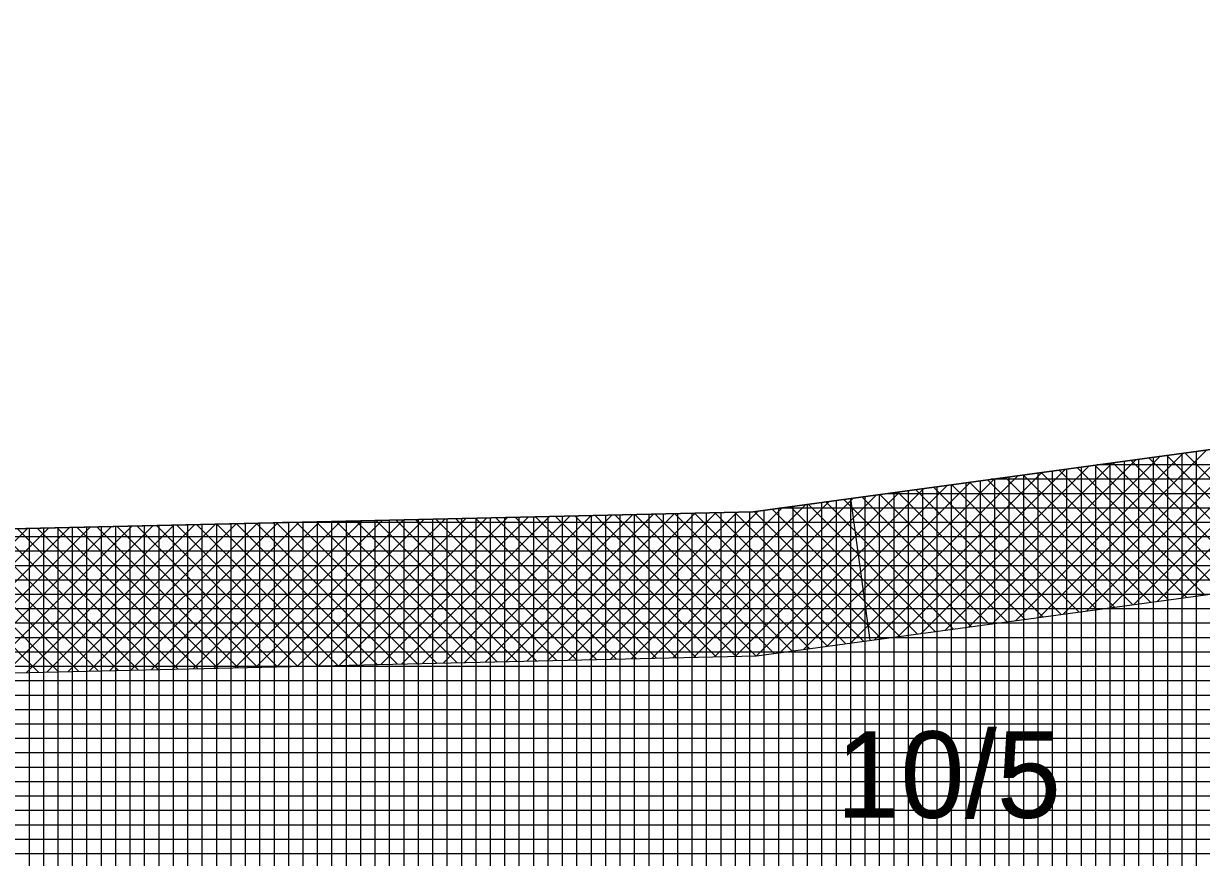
# Model space of a CAD drawing. Extents: x -565346 to -564154, y -1097386 to -1095620.
# Drawn here: x -565241.4 to -565225.05, y -1095860.99 to -1095849.41 of the extents above; entities that cross this region are included whole.
import ezdxf

# ---------------------------------------------------------------- set-up
doc = ezdxf.new("R2010")
doc.units = 0
for name, color, linetype in [('Vrstva 13', 7, 'Continuous'), ('Vrstva 40', 7, 'Continuous'), ('Vrstva 41', 7, 'Continuous'), ('Vrstva 42', 7, 'Continuous'), ('Vrstva 43', 7, 'Continuous')]:
    doc.layers.add(name, color=color, linetype=linetype)

msp = doc.modelspace()

# ---------------------------------------------------------------- linework, layer by layer
at = {"layer": 'Vrstva 13'}
for p, q in [((-565231.27, -1095856.19), (-565188.3, -1095850.34)), ((-565311.82, -1095858.04), (-565231.27, -1095856.19))]:
    msp.add_line(p, q, dxfattribs=at)
at = {"layer": 'Vrstva 41'}
for p, q in [((-565223.663, -1095855.154), (-565225.986, -1095857.478)), ((-565223.336, -1095855.11), (-565225.659, -1095857.433)), ((-565223.008, -1095855.065), (-565225.332, -1095857.389)), ((-565224.973, -1095855.333), (-565227.295, -1095857.655)), ((-565224.645, -1095855.288), (-565226.968, -1095857.611)), ((-565224.318, -1095855.244), (-565226.641, -1095857.567)), ((-565223.99, -1095855.199), (-565226.314, -1095857.522)), ((-565226.282, -1095855.511), (-565228.605, -1095857.833)), ((-565225.955, -1095855.466), (-565228.277, -1095857.789)), ((-565225.628, -1095855.422), (-565227.95, -1095857.744)), ((-565225.3, -1095855.377), (-565227.623, -1095857.7)), ((-565224.51, -1095857.277), (-565226.277, -1095855.51)), ((-565224.261, -1095857.243), (-565226.028, -1095855.476)), ((-565224.012, -1095857.209), (-565225.779, -1095855.442)), ((-565223.763, -1095857.176), (-565225.53, -1095855.409)), ((-565223.514, -1095857.142), (-565225.281, -1095855.375)), ((-565227.265, -1095855.645), (-565229.587, -1095857.967)), ((-565226.937, -1095855.6), (-565229.259, -1095857.922)), ((-565226.61, -1095855.556), (-565228.932, -1095857.878)), ((-565225.755, -1095857.446), (-565227.521, -1095855.68)), ((-565225.506, -1095857.412), (-565227.272, -1095855.646)), ((-565225.257, -1095857.379), (-565227.024, -1095855.612)), ((-565225.008, -1095857.345), (-565226.775, -1095855.578)), ((-565224.759, -1095857.311), (-565226.526, -1095855.544)), ((-565228.574, -1095855.823), (-565230.896, -1095858.144)), ((-565228.247, -1095855.778), (-565230.568, -1095858.1)), ((-565227.919, -1095855.734), (-565230.241, -1095858.056)), ((-565227.592, -1095855.689), (-565229.914, -1095858.011)), ((-565226.751, -1095857.581), (-565228.517, -1095855.815)), ((-565226.502, -1095857.548), (-565228.268, -1095855.781)), ((-565226.253, -1095857.514), (-565228.019, -1095855.747)), ((-565226.004, -1095857.48), (-565227.77, -1095855.714)), ((-565229.884, -1095856.001), (-565232.092, -1095858.209)), ((-565229.557, -1095855.957), (-565231.802, -1095858.202)), ((-565229.229, -1095855.912), (-565231.513, -1095858.196)), ((-565228.902, -1095855.868), (-565231.223, -1095858.189)), ((-565227.996, -1095857.751), (-565229.762, -1095855.985)), ((-565227.747, -1095857.717), (-565229.513, -1095855.951)), ((-565227.498, -1095857.683), (-565229.264, -1095855.917)), ((-565227.249, -1095857.649), (-565229.015, -1095855.883)), ((-565227, -1095857.615), (-565228.766, -1095855.849)), ((-565230.866, -1095856.135), (-565232.96, -1095858.229)), ((-565230.539, -1095856.09), (-565232.671, -1095858.222)), ((-565230.211, -1095856.046), (-565232.381, -1095858.216)), ((-565229.241, -1095857.92), (-565231.007, -1095856.154)), ((-565228.992, -1095857.886), (-565230.758, -1095856.12)), ((-565228.743, -1095857.852), (-565230.509, -1095856.086)), ((-565228.494, -1095857.818), (-565230.26, -1095856.052)), ((-565228.245, -1095857.784), (-565230.011, -1095856.019)), ((-565237.571, -1095856.335), (-565239.618, -1095858.382)), ((-565237.282, -1095856.328), (-565239.329, -1095858.375)), ((-565236.992, -1095856.321), (-565239.039, -1095858.368)), ((-565236.703, -1095856.315), (-565238.75, -1095858.362)), ((-565236.413, -1095856.308), (-565238.46, -1095858.355)), ((-565236.124, -1095856.301), (-565238.171, -1095858.349)), ((-565235.834, -1095856.295), (-565237.881, -1095858.342)), ((-565235.658, -1095858.291), (-565237.613, -1095856.336)), ((-565235.545, -1095856.288), (-565237.592, -1095858.335)), ((-565235.382, -1095858.284), (-565237.337, -1095856.329)), ((-565235.255, -1095856.282), (-565237.302, -1095858.329)), ((-565235.105, -1095858.278), (-565237.06, -1095856.323)), ((-565234.966, -1095856.275), (-565237.013, -1095858.322)), ((-565234.829, -1095858.272), (-565236.784, -1095856.317)), ((-565234.676, -1095856.268), (-565236.723, -1095858.315)), ((-565234.552, -1095858.265), (-565236.507, -1095856.31)), ((-565234.387, -1095856.262), (-565236.434, -1095858.309)), ((-565234.276, -1095858.259), (-565236.231, -1095856.304)), ((-565234.097, -1095856.255), (-565236.145, -1095858.302)), ((-565233.999, -1095858.253), (-565235.954, -1095856.298)), ((-565233.808, -1095856.248), (-565235.855, -1095858.295)), ((-565233.723, -1095858.246), (-565235.678, -1095856.291)), ((-565233.518, -1095856.242), (-565235.566, -1095858.289)), ((-565233.446, -1095858.24), (-565235.401, -1095856.285)), ((-565233.229, -1095856.235), (-565235.276, -1095858.282)), ((-565233.17, -1095858.234), (-565235.125, -1095856.279)), ((-565232.939, -1095856.228), (-565234.987, -1095858.275)), ((-565232.893, -1095858.227), (-565234.848, -1095856.272)), ((-565232.65, -1095856.222), (-565234.697, -1095858.269)), ((-565232.617, -1095858.221), (-565234.572, -1095856.266)), ((-565232.36, -1095856.215), (-565234.408, -1095858.262)), ((-565232.34, -1095858.215), (-565234.295, -1095856.259)), ((-565232.071, -1095856.208), (-565234.118, -1095858.255)), ((-565232.064, -1095858.208), (-565234.019, -1095856.253)), ((-565231.782, -1095856.202), (-565233.829, -1095858.249)), ((-565231.787, -1095858.202), (-565233.743, -1095856.247)), ((-565231.492, -1095856.195), (-565233.539, -1095858.242)), ((-565231.511, -1095858.196), (-565233.466, -1095856.24)), ((-565231.194, -1095856.18), (-565233.25, -1095858.236)), ((-565231.234, -1095858.189), (-565233.19, -1095856.234)), ((-565230.984, -1095858.156), (-565232.913, -1095856.228)), ((-565230.735, -1095858.123), (-565232.637, -1095856.221)), ((-565230.486, -1095858.089), (-565232.36, -1095856.215)), ((-565230.237, -1095858.055), (-565232.084, -1095856.209)), ((-565229.988, -1095858.021), (-565231.807, -1095856.202)), ((-565229.739, -1095857.987), (-565231.531, -1095856.196)), ((-565229.49, -1095857.954), (-565231.256, -1095856.188)), ((-565241.335, -1095856.421), (-565243.382, -1095858.468)), ((-565241.188, -1095858.418), (-565243.143, -1095856.463)), ((-565241.045, -1095856.415), (-565243.092, -1095858.462)), ((-565240.912, -1095858.411), (-565242.867, -1095856.456)), ((-565240.756, -1095856.408), (-565242.803, -1095858.455)), ((-565240.635, -1095858.405), (-565242.59, -1095856.45)), ((-565240.466, -1095856.401), (-565242.513, -1095858.448)), ((-565240.359, -1095858.399), (-565242.314, -1095856.444)), ((-565240.177, -1095856.395), (-565242.224, -1095858.442)), ((-565240.082, -1095858.392), (-565242.037, -1095856.437)), ((-565239.887, -1095856.388), (-565241.934, -1095858.435)), ((-565239.806, -1095858.386), (-565241.761, -1095856.431)), ((-565239.598, -1095856.381), (-565241.645, -1095858.428)), ((-565239.529, -1095858.38), (-565241.484, -1095856.425)), ((-565239.308, -1095856.375), (-565241.355, -1095858.422)), ((-565239.253, -1095858.373), (-565241.208, -1095856.418)), ((-565239.019, -1095856.368), (-565241.066, -1095858.415)), ((-565238.976, -1095858.367), (-565240.931, -1095856.412)), ((-565238.729, -1095856.361), (-565240.776, -1095858.408)), ((-565238.7, -1095858.361), (-565240.655, -1095856.406)), ((-565238.44, -1095856.355), (-565240.487, -1095858.402)), ((-565238.423, -1095858.354), (-565240.378, -1095856.399)), ((-565238.15, -1095856.348), (-565240.197, -1095858.395)), ((-565238.147, -1095858.348), (-565240.102, -1095856.393)), ((-565237.861, -1095856.341), (-565239.908, -1095858.388)), ((-565237.87, -1095858.342), (-565239.825, -1095856.386)), ((-565237.594, -1095858.335), (-565239.549, -1095856.38)), ((-565237.317, -1095858.329), (-565239.272, -1095856.374)), ((-565237.041, -1095858.323), (-565238.996, -1095856.367)), ((-565236.764, -1095858.316), (-565238.719, -1095856.361)), ((-565236.488, -1095858.31), (-565238.443, -1095856.355)), ((-565236.211, -1095858.304), (-565238.166, -1095856.348)), ((-565235.935, -1095858.297), (-565237.89, -1095856.342))]:
    msp.add_line(p, q, dxfattribs=at)
at = {"layer": 'Vrstva 42'}
msp.add_line((-565229.648, -1095857.975), (-565229.916, -1095856.006), dxfattribs=at)
msp.add_lwpolyline([(-565180.166, -1095851.786), (-565180.303, -1095849.791), (-565188.3, -1095850.34), (-565231.27, -1095856.19), (-565311.82, -1095858.04), (-565322.62, -1095856.13), (-565322.968, -1095858.099), (-565311.774, -1095860.039), (-565231.224, -1095858.189), (-565188.087, -1095852.33)], close=True, dxfattribs=at)
at = {"layer": 'Vrstva 43'}
for p, q in [((-565225.12, -1095855.353), (-565225.12, -1095870.54)), ((-565226.32, -1095855.516), (-565226.32, -1095870.674)), ((-565226.12, -1095855.489), (-565226.12, -1095870.652)), ((-565225.92, -1095855.462), (-565225.92, -1095870.63)), ((-565225.72, -1095855.434), (-565225.72, -1095870.607)), ((-565225.52, -1095855.407), (-565225.52, -1095870.585)), ((-565225.32, -1095855.38), (-565225.32, -1095870.563)), ((-565227.52, -1095855.679), (-565227.52, -1095870.809)), ((-565227.32, -1095855.652), (-565227.32, -1095870.786)), ((-565227.12, -1095855.625), (-565227.12, -1095870.764)), ((-565226.92, -1095855.598), (-565226.92, -1095870.741)), ((-565226.72, -1095855.571), (-565226.72, -1095870.719)), ((-565226.52, -1095855.543), (-565226.52, -1095870.697)), ((-565091.015, -1095855.54), (-565226.496, -1095855.54)), ((-565228.72, -1095855.843), (-565228.72, -1095870.943)), ((-565228.52, -1095855.816), (-565228.52, -1095870.92)), ((-565228.32, -1095855.788), (-565228.32, -1095870.898)), ((-565228.12, -1095855.761), (-565228.12, -1095870.876)), ((-565092.803, -1095855.74), (-565227.965, -1095855.74)), ((-565227.92, -1095855.734), (-565227.92, -1095870.853)), ((-565227.72, -1095855.707), (-565227.72, -1095870.831)), ((-565229.92, -1095856.006), (-565229.92, -1095871.077)), ((-565229.72, -1095855.979), (-565229.72, -1095871.055)), ((-565229.52, -1095855.952), (-565229.52, -1095871.032)), ((-565094.591, -1095855.94), (-565229.434, -1095855.94)), ((-565229.32, -1095855.925), (-565229.32, -1095871.01)), ((-565229.12, -1095855.897), (-565229.12, -1095870.988)), ((-565228.92, -1095855.87), (-565228.92, -1095870.965)), ((-565231.12, -1095856.17), (-565231.12, -1095871.194)), ((-565230.92, -1095856.142), (-565230.92, -1095871.189)), ((-565096.379, -1095856.14), (-565230.903, -1095856.14)), ((-565230.72, -1095856.115), (-565230.72, -1095871.167)), ((-565230.52, -1095856.088), (-565230.52, -1095871.144)), ((-565230.32, -1095856.061), (-565230.32, -1095871.122)), ((-565230.12, -1095856.033), (-565230.12, -1095871.099)), ((-565237.52, -1095856.334), (-565237.52, -1095871.341)), ((-565237.32, -1095856.329), (-565237.32, -1095871.336)), ((-565237.12, -1095856.324), (-565237.12, -1095871.332)), ((-565236.92, -1095856.32), (-565236.92, -1095871.327)), ((-565236.72, -1095856.315), (-565236.72, -1095871.323)), ((-565236.52, -1095856.311), (-565236.52, -1095871.318)), ((-565236.32, -1095856.306), (-565236.32, -1095871.313)), ((-565236.12, -1095856.301), (-565236.12, -1095871.309)), ((-565235.92, -1095856.297), (-565235.92, -1095871.304)), ((-565235.72, -1095856.292), (-565235.72, -1095871.3)), ((-565235.52, -1095856.288), (-565235.52, -1095871.295)), ((-565235.32, -1095856.283), (-565235.32, -1095871.291)), ((-565235.12, -1095856.278), (-565235.12, -1095871.286)), ((-565234.92, -1095856.274), (-565234.92, -1095871.281)), ((-565234.72, -1095856.269), (-565234.72, -1095871.277)), ((-565234.52, -1095856.265), (-565234.52, -1095871.272)), ((-565234.32, -1095856.26), (-565234.32, -1095871.268)), ((-565234.12, -1095856.255), (-565234.12, -1095871.263)), ((-565233.92, -1095856.251), (-565233.92, -1095871.258)), ((-565233.72, -1095856.246), (-565233.72, -1095871.254)), ((-565233.52, -1095856.242), (-565233.52, -1095871.249)), ((-565233.32, -1095856.237), (-565233.32, -1095871.245)), ((-565233.12, -1095856.232), (-565233.12, -1095871.24)), ((-565232.92, -1095856.228), (-565232.92, -1095871.236)), ((-565232.72, -1095856.223), (-565232.72, -1095871.231)), ((-565232.52, -1095856.219), (-565232.52, -1095871.226)), ((-565232.32, -1095856.214), (-565232.32, -1095871.222)), ((-565232.12, -1095856.21), (-565232.12, -1095871.217)), ((-565231.92, -1095856.205), (-565231.92, -1095871.213)), ((-565231.72, -1095856.2), (-565231.72, -1095871.208)), ((-565231.52, -1095856.196), (-565231.52, -1095871.204)), ((-565231.32, -1095856.191), (-565231.32, -1095871.199)), ((-565241.32, -1095856.421), (-565241.32, -1095871.428)), ((-565241.12, -1095856.416), (-565241.12, -1095871.423)), ((-565240.92, -1095856.412), (-565240.92, -1095871.419)), ((-565240.72, -1095856.407), (-565240.72, -1095871.414)), ((-565240.52, -1095856.402), (-565240.52, -1095871.41)), ((-565240.32, -1095856.398), (-565240.32, -1095871.405)), ((-565240.12, -1095856.393), (-565240.12, -1095871.4)), ((-565239.92, -1095856.389), (-565239.92, -1095871.396)), ((-565239.72, -1095856.384), (-565239.72, -1095871.391)), ((-565239.52, -1095856.379), (-565239.52, -1095871.387)), ((-565239.32, -1095856.375), (-565239.32, -1095871.382)), ((-565239.12, -1095856.37), (-565239.12, -1095871.378)), ((-565238.92, -1095856.366), (-565238.92, -1095871.373)), ((-565238.72, -1095856.361), (-565238.72, -1095871.368)), ((-565238.52, -1095856.357), (-565238.52, -1095871.364)), ((-565238.32, -1095856.352), (-565238.32, -1095871.359)), ((-565238.12, -1095856.347), (-565238.12, -1095871.355)), ((-565237.92, -1095856.343), (-565237.92, -1095871.35)), ((-565098.167, -1095856.34), (-565237.801, -1095856.34)), ((-565237.72, -1095856.338), (-565237.72, -1095871.345)), ((-565099.955, -1095856.54), (-565246.509, -1095856.54)), ((-565101.743, -1095856.74), (-565255.217, -1095856.74)), ((-565103.531, -1095856.94), (-565263.925, -1095856.94)), ((-565105.319, -1095857.14), (-565272.634, -1095857.14)), ((-565107.107, -1095857.34), (-565281.342, -1095857.34)), ((-565108.895, -1095857.54), (-565290.05, -1095857.54)), ((-565110.683, -1095857.74), (-565298.758, -1095857.74)), ((-565112.472, -1095857.94), (-565307.466, -1095857.94)), ((-565114.26, -1095858.14), (-565322.58, -1095858.14)), ((-565116.048, -1095858.34), (-565322.576, -1095858.34)), ((-565117.836, -1095858.54), (-565322.572, -1095858.54)), ((-565119.624, -1095858.74), (-565322.568, -1095858.74)), ((-565121.412, -1095858.94), (-565322.564, -1095858.94)), ((-565123.2, -1095859.14), (-565322.56, -1095859.14)), ((-565124.988, -1095859.34), (-565322.556, -1095859.34)), ((-565126.776, -1095859.54), (-565322.552, -1095859.54)), ((-565128.564, -1095859.74), (-565322.548, -1095859.74)), ((-565130.352, -1095859.94), (-565322.544, -1095859.94)), ((-565132.14, -1095860.14), (-565322.541, -1095860.14)), ((-565133.928, -1095860.34), (-565322.537, -1095860.34)), ((-565135.716, -1095860.54), (-565322.533, -1095860.54)), ((-565137.504, -1095860.74), (-565322.529, -1095860.74)), ((-565139.292, -1095860.94), (-565322.525, -1095860.94))]:
    msp.add_line(p, q, dxfattribs=at)
msp.add_lwpolyline([(-565311.82, -1095858.04), (-565322.62, -1095856.13), (-565322.28, -1095873.28), (-565318.28, -1095873.19), (-565230.93, -1095871.19), (-565052.84, -1095851.27), (-565052.77, -1095836.13), (-565130.42, -1095846.37), (-565188.3, -1095850.34), (-565231.27, -1095856.19)], close=True, dxfattribs=at)

# ---------------------------------------------------------------- texts
at = {"layer": 'Vrstva 40'}
msp.add_text('10/5', height=1.2, dxfattribs=at).set_placement((-565230.12, -1095860.44))

doc.saveas('drawing.dxf')
